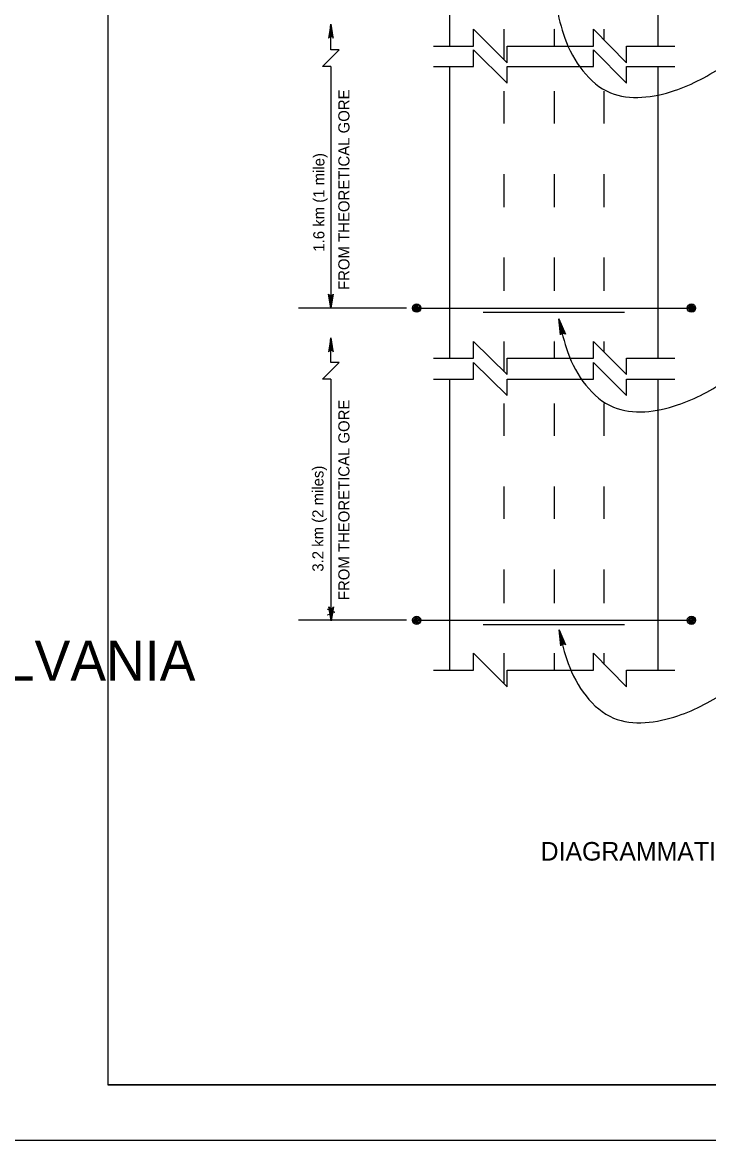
# Model space of a CAD drawing. Extents: x 640994 to 644422, y 298458 to 299646.
# Drawn here: x 641852.3 to 642036.9, y 298457.6 to 298758.5 of the extents above; entities that cross this region are included whole.
import ezdxf

# ---------------------------------------------------------------- set-up
doc = ezdxf.new("R2010")
doc.units = 0
for name, color, linetype in [('1', 7, 'Continuous'), ('2', 7, 'Continuous'), ('XCS-GRID-MIN', 7, 'Continuous')]:
    doc.layers.add(name, color=color, linetype=linetype)

msp = doc.modelspace()

# ---------------------------------------------------------------- linework, layer by layer
at = {"layer": '1'}
for p, q in [((641875.31, 299036.63), (641875.31, 298472.63)), ((642661.31, 298472.63), (641875.31, 298472.63)), ((641875.31, 298472.63), (642461.31, 298472.63))]:
    msp.add_line(p, q, dxfattribs=at)
at = {"layer": '2'}
for p, q in [((641967.31, 298752.13), (641967.31, 298830.5)), ((642023.31, 298752.13), (642023.31, 298830.5)), ((641995.44, 298756.75), (641995.44, 298756.75)), ((641981.94, 298748.5), (641981.94, 298756.63)), ((641995.44, 298756.63), (641995.44, 298756.63)), ((641995.44, 298752.13), (641995.44, 298756.63)), ((642008.81, 298753.75), (642008.81, 298756.63)), ((641962.94, 298752.13), (641973.69, 298752.13)), ((641982.69, 298752.13), (642005.94, 298752.13)), ((642014.81, 298752.13), (642027.81, 298752.13)), ((641935.31, 298746.63), (641935.31, 298681.63)), ((641962.94, 298746.63), (641973.69, 298746.63)), ((641967.31, 298668.13), (641967.31, 298746.63)), ((641982.69, 298746.63), (642005.94, 298746.63)), ((642014.81, 298746.63), (642027.81, 298746.63)), ((642023.31, 298668.13), (642023.31, 298746.63)), ((641981.94, 298731.25), (641981.94, 298740)), ((641995.44, 298740), (641995.44, 298740)), ((641995.44, 298731.25), (641995.44, 298740)), ((642008.81, 298731.25), (642008.81, 298740)), ((641995.44, 298731.25), (641995.44, 298731.25)), ((641981.94, 298708.75), (641981.94, 298717.63)), ((641995.44, 298717.63), (641995.44, 298717.63)), ((641995.44, 298708.75), (641995.44, 298717.63)), ((642008.81, 298708.75), (642008.81, 298717.63)), ((641995.44, 298708.75), (641995.44, 298708.75)), ((641981.94, 298686.25), (641981.94, 298695.25)), ((641995.44, 298695.25), (641995.44, 298695.25)), ((641995.44, 298686.25), (641995.44, 298695.25)), ((642008.81, 298686.25), (642008.81, 298695.25)), ((641995.44, 298686.38), (641995.44, 298686.38)), ((641995.44, 298686.25), (641995.44, 298686.25)), ((641955.69, 298681.63), (641926.56, 298681.63)), ((641959.19, 298681.88), (641957.44, 298681.5)), ((641958.19, 298680.63), (641957.44, 298681.75)), ((641957.44, 298681.75), (641958.81, 298680.63)), ((641957.44, 298681.5), (641959.31, 298681.5)), ((641958.81, 298682.38), (641957.56, 298681.88)), ((641957.56, 298681.88), (641959.19, 298681.88)), ((641959.31, 298681.5), (641957.69, 298681)), ((641957.81, 298682.38), (641958.81, 298682.38)), ((641958.81, 298680.63), (641958.19, 298682.5)), ((641958.19, 298682.5), (641959.31, 298681.25)), ((641958.44, 298681.63), (642032.31, 298681.63)), ((641958.44, 298681.63), (641958.44, 298681.63)), ((641959.31, 298681.25), (641959.06, 298682.5)), ((642032.94, 298681.88), (642031.31, 298681.5)), ((642032.19, 298680.63), (642031.31, 298681.75)), ((642031.31, 298681.75), (642032.81, 298680.63)), ((642031.31, 298681.5), (642033.19, 298681.5)), ((642032.69, 298682.38), (642031.44, 298681.88)), ((642031.44, 298681.88), (642032.94, 298681.88)), ((642033.19, 298681.5), (642031.56, 298681)), ((642031.69, 298682.38), (642032.69, 298682.38)), ((642032.81, 298680.63), (642032.19, 298682.5)), ((642032.19, 298682.5), (642033.19, 298681.25)), ((642032.31, 298681.63), (642032.31, 298681.63)), ((642033.19, 298681.25), (642032.94, 298682.5)), ((641957.69, 298681), (641959.19, 298681.13)), ((641959.19, 298681.13), (641958.19, 298680.63)), ((641976.31, 298680.5), (642014.31, 298680.5)), ((642031.56, 298681), (642033.06, 298681.13)), ((642033.06, 298681.13), (642032.19, 298680.63)), ((641981.94, 298664.5), (641981.94, 298672.63)), ((641995.44, 298672.88), (641995.44, 298672.88)), ((641995.44, 298672.63), (641995.44, 298672.63)), ((641995.44, 298668.13), (641995.44, 298672.63)), ((642008.81, 298669.88), (642008.81, 298672.63)), ((641962.94, 298668.13), (641973.69, 298668.13)), ((641982.69, 298668.13), (642005.94, 298668.13)), ((642014.81, 298668.13), (642027.81, 298668.13)), ((641935.31, 298662.5), (641935.31, 298597.63)), ((641962.94, 298662.5), (641973.69, 298662.5)), ((641967.31, 298584.25), (641967.31, 298662.5)), ((641982.69, 298662.5), (642005.94, 298662.5)), ((642014.81, 298662.5), (642027.81, 298662.5)), ((642023.31, 298584.25), (642023.31, 298662.5)), ((641981.94, 298647.25), (641981.94, 298656)), ((641995.44, 298656), (641995.44, 298656)), ((641995.44, 298647.25), (641995.44, 298656)), ((642008.81, 298647.25), (642008.81, 298656)), ((641995.44, 298647.25), (641995.44, 298647.25)), ((641981.94, 298624.88), (641981.94, 298633.63)), ((641995.44, 298633.63), (641995.44, 298633.63)), ((641995.44, 298624.88), (641995.44, 298633.63)), ((642008.81, 298624.88), (642008.81, 298633.63)), ((641995.44, 298624.88), (641995.44, 298624.88)), ((641981.94, 298602.25), (641981.94, 298611.25)), ((641995.44, 298611.25), (641995.44, 298611.25)), ((641995.44, 298602.25), (641995.44, 298611.25)), ((642008.81, 298602.25), (642008.81, 298611.25)), ((641995.44, 298602.5), (641995.44, 298602.5)), ((641995.44, 298602.25), (641995.44, 298602.25)), ((641955.69, 298597.63), (641926.56, 298597.63)), ((641959.19, 298597.75), (641957.44, 298597.5)), ((641958.19, 298596.75), (641957.44, 298597.75)), ((641957.44, 298597.75), (641958.81, 298596.75)), ((641957.44, 298597.5), (641959.31, 298597.5)), ((641958.81, 298598.25), (641957.56, 298597.88)), ((641957.56, 298597.88), (641959.19, 298597.75)), ((641959.31, 298597.5), (641957.69, 298597)), ((641957.81, 298598.25), (641958.81, 298598.25)), ((641958.81, 298596.75), (641958.19, 298598.63)), ((641958.19, 298598.63), (641959.31, 298597.38)), ((641958.44, 298597.63), (642032.31, 298597.63)), ((641958.44, 298597.63), (641958.44, 298597.63)), ((641959.31, 298597.38), (641959.06, 298598.5)), ((642032.94, 298597.75), (642031.31, 298597.5)), ((642032.19, 298596.75), (642031.31, 298597.75)), ((642031.31, 298597.75), (642032.81, 298596.75)), ((642031.31, 298597.5), (642033.19, 298597.5)), ((642032.69, 298598.25), (642031.44, 298597.88)), ((642031.44, 298597.88), (642032.94, 298597.75)), ((642033.19, 298597.5), (642031.56, 298597)), ((642031.69, 298598.25), (642032.69, 298598.25)), ((642032.81, 298596.75), (642032.19, 298598.63)), ((642032.19, 298598.63), (642033.19, 298597.38)), ((642032.31, 298597.63), (642032.31, 298597.63)), ((642033.19, 298597.38), (642032.94, 298598.5)), ((641957.69, 298597), (641959.19, 298597)), ((641959.19, 298597), (641958.19, 298596.75)), ((641976.31, 298596.5), (642014.31, 298596.5)), ((642031.56, 298597), (642033.06, 298597)), ((642033.06, 298597), (642032.19, 298596.75)), ((641981.94, 298580.63), (641981.94, 298588.75)), ((641995.44, 298588.75), (641995.44, 298588.75)), ((641995.44, 298588.75), (641995.44, 298588.75)), ((641995.44, 298584.25), (641995.44, 298588.75)), ((642008.81, 298585.75), (642008.81, 298588.75)), ((641962.94, 298584.25), (641973.69, 298584.25)), ((641967.31, 298584.25), (641967.31, 298584.25)), ((641982.69, 298584.25), (642005.94, 298584.25)), ((642014.81, 298584.25), (642027.81, 298584.25))]:
    msp.add_line(p, q, dxfattribs=at)
for points in [[(641935.31, 298746.63), (641933.06, 298746.63), (641937.56, 298751.13), (641935.31, 298751.13), (641935.31, 298758)], [(641935.81, 298754.5), (641935.56, 298754.63), (641935.31, 298758), (641935.81, 298754.5), (641935.94, 298754.25), (641935.31, 298758), (641935.19, 298754.63), (641934.94, 298754.5), (641935.31, 298758), (641934.69, 298754.25), (641934.94, 298754.5)], [(641973.69, 298752.13), (641973.69, 298756.63), (641982.69, 298747.63), (641982.69, 298752.13)], [(642005.94, 298752.13), (642005.94, 298756.63), (642014.81, 298747.63), (642014.81, 298752.13)], [(641973.69, 298746.63), (641973.69, 298751.13), (641982.69, 298742.13), (641982.69, 298746.63)], [(642005.94, 298746.63), (642005.94, 298751.13), (642014.81, 298742.13), (642014.81, 298746.63)], [(641935.81, 298685.13), (641935.56, 298685), (641935.31, 298681.63), (641935.81, 298685.13), (641935.94, 298685.38), (641935.31, 298681.63), (641935.19, 298685), (641934.94, 298685.13), (641935.31, 298681.63), (641934.69, 298685.38), (641934.94, 298685.13)], [(641997.16, 298674.65), (641997.54, 298674.89), (641996.64, 298678.71), (641997.16, 298674.65), (641997.06, 298674.42), (641996.64, 298678.71), (641997.82, 298674.9), (641998.21, 298674.86), (641996.64, 298678.71), (641998.39, 298674.65), (641998.21, 298674.86)], [(641935.31, 298662.5), (641933.06, 298662.5), (641937.56, 298667), (641935.31, 298667), (641935.31, 298673.63)], [(641935.81, 298670.13), (641935.56, 298670.25), (641935.31, 298673.63), (641935.81, 298670.13), (641935.94, 298669.88), (641935.31, 298673.63), (641935.19, 298670.25), (641934.94, 298670.13), (641935.31, 298673.63), (641934.69, 298669.88), (641934.94, 298670.13)], [(641973.69, 298668.13), (641973.69, 298672.63), (641982.69, 298663.75), (641982.69, 298668.13)], [(642005.94, 298668.13), (642005.94, 298672.63), (642014.81, 298663.75), (642014.81, 298668.13)], [(641973.69, 298662.5), (641973.69, 298667), (641982.69, 298658.13), (641982.69, 298662.5)], [(642005.94, 298662.5), (642005.94, 298667), (642014.81, 298658.13), (642014.81, 298662.5)], [(641935.91, 298601.02), (641935.66, 298600.89), (641935.41, 298597.52), (641935.91, 298601.02), (641936.03, 298601.27), (641935.41, 298597.52), (641935.28, 298600.89), (641935.03, 298601.02), (641935.41, 298597.52), (641934.78, 298601.27), (641935.03, 298601.02)], [(641997.23, 298591.01), (641997.61, 298591.25), (641996.71, 298595.07), (641997.23, 298591.01), (641997.13, 298590.78), (641996.71, 298595.07), (641997.89, 298591.26), (641998.28, 298591.22), (641996.71, 298595.07), (641998.46, 298591), (641998.28, 298591.22)], [(641973.69, 298584.25), (641973.69, 298588.75), (641982.69, 298579.75), (641982.69, 298584.25)], [(642005.94, 298584.25), (642005.94, 298588.75), (642014.81, 298579.75), (642014.81, 298584.25)]]:
    msp.add_lwpolyline(points, dxfattribs=at)
for centre in [(641958.39, 298681.61), (642032.29, 298681.61), (641958.39, 298597.63), (642032.29, 298597.63)]:
    msp.add_circle(centre, 1.12, dxfattribs=at)
for points in [[(641995.94, 298762.88), (641998.23, 298754.26), (642010.49, 298739.55), (642027.72, 298740.15), (642041.21, 298747.03), (642053.43, 298756.45), (642063.69, 298765.5)], [(641996.75, 298678.29), (641999.04, 298669.68), (642011.3, 298654.97), (642028.53, 298655.56), (642042.03, 298662.45), (642054.24, 298671.87), (642064.5, 298680.92)], [(641996.82, 298594.65), (641999.12, 298586.04), (642011.37, 298571.33), (642028.6, 298571.92), (642042.1, 298578.81), (642054.31, 298588.23), (642064.57, 298597.28)]]:
    msp.add_spline(points, degree=3, dxfattribs=at)
at = {"layer": 'XCS-GRID-MIN'}
msp.add_lwpolyline([(641835.31, 299051.63), (642676.31, 299051.63), (642676.31, 298457.63), (641835.31, 298457.63)], close=True, dxfattribs=at)

# ---------------------------------------------------------------- texts
at = {"layer": '1'}
msp.add_text('COMMONWEALTH OF PENNSYLVANIA', height=10.7828, dxfattribs=at).set_placement((641632.9, 298581.36))
at = {"layer": '2'}
for s, height, rotation, p in [('FROM THEORETICAL GORE', 3, 90, (641940.31, 298686.51)), ('1.6 km (1 mile) ', 3, 90, (641933.57, 298696.81)), ('FROM THEORETICAL GORE', 3, 90, (641940.31, 298603.05)), ('3.2 km (2 miles)', 3, 90, (641933.32, 298610.7)), ('A', 2.09, 270, (641934.31, 298600.75))]:
    msp.add_text(s, height=height, rotation=rotation, dxfattribs=at).set_placement(p)
msp.add_text('DIAGRAMMATIC SIGNING', height=5, dxfattribs=at).set_placement((641991.72, 298532.97))

doc.saveas('drawing.dxf')
